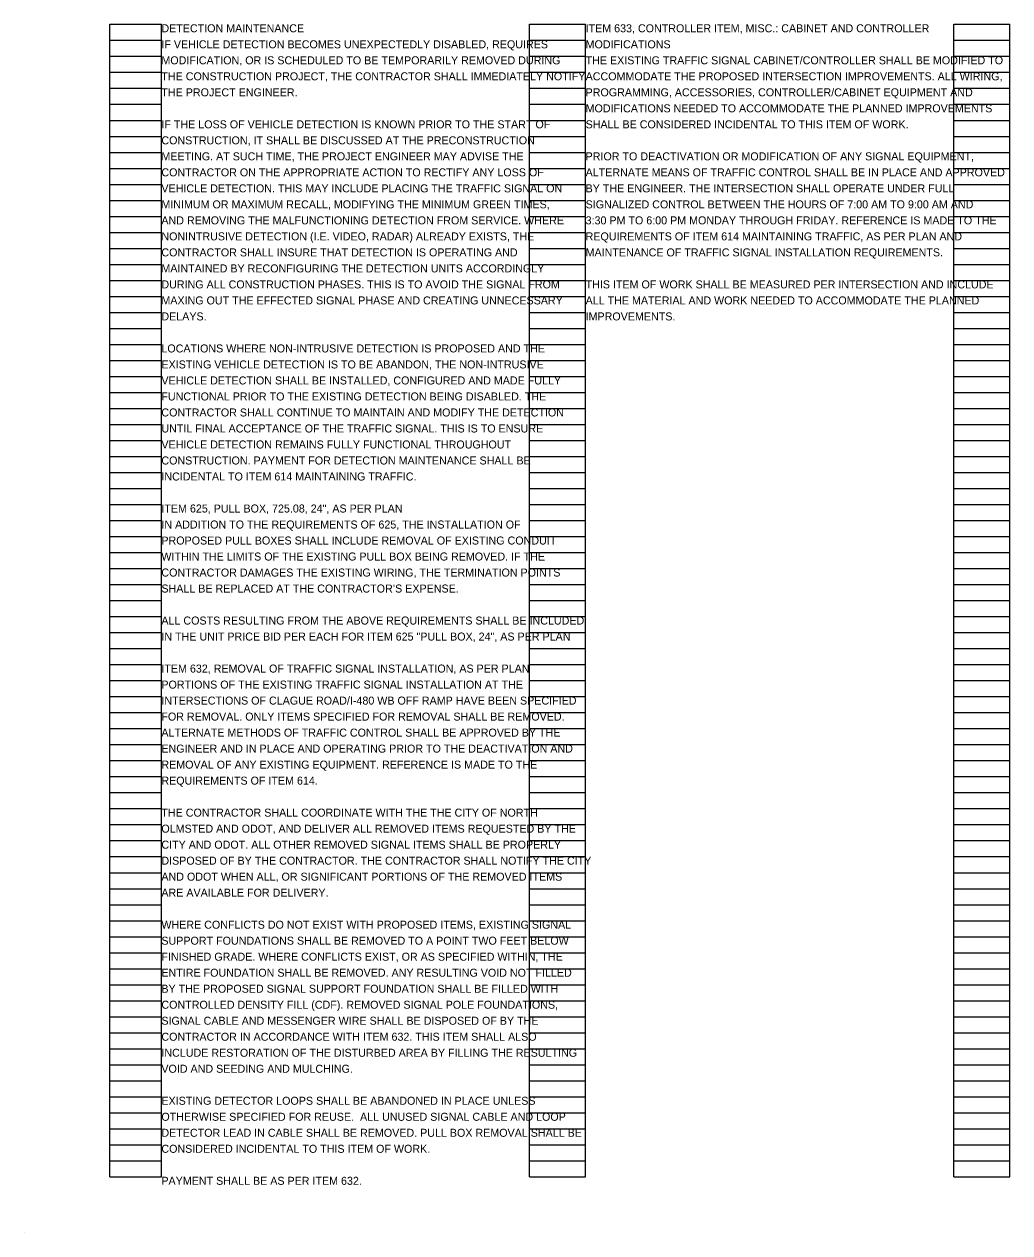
# Model space of a CAD drawing. Extents: x 0 to 34, y -30 to 22.
# Drawn here: x 0 to 17.24, y -30 to -8.86 of the extents above; entities that cross this region are included whole.
import ezdxf

# ---------------------------------------------------------------- set-up
doc = ezdxf.new("R2010")
doc.units = 0
doc.layers.add('SH_Data', color=7, linetype='Continuous')
doc.layers.add('SH_Text', color=7, linetype='Continuous')

msp = doc.modelspace()

# ---------------------------------------------------------------- linework, layer by layer
at = {"layer": 'SH_Data'}
for p, q in [((1.5, -29.02), (1.5, -8.86)), ((1.5, -8.86), (2.4, -8.86)), ((2.4, -29.02), (2.4, -8.86)), ((8.84, -29.02), (8.84, -8.86)), ((8.84, -8.86), (9.82, -8.86)), ((9.82, -29.02), (9.82, -8.86)), ((16.26, -29.02), (16.26, -8.86)), ((16.26, -8.86), (17.24, -8.86)), ((17.24, -29.02), (17.24, -8.86)), ((1.5, -9.14), (2.4, -9.14)), ((8.84, -9.14), (9.82, -9.14)), ((16.26, -9.14), (17.24, -9.14)), ((1.5, -9.42), (2.4, -9.42)), ((8.84, -9.42), (9.82, -9.42)), ((16.26, -9.42), (17.24, -9.42)), ((1.5, -9.7), (2.4, -9.7)), ((8.84, -9.7), (9.82, -9.7)), ((16.26, -9.7), (17.24, -9.7)), ((1.5, -9.98), (2.4, -9.98)), ((8.84, -9.98), (9.82, -9.98)), ((16.26, -9.98), (17.24, -9.98)), ((1.5, -10.26), (2.4, -10.26)), ((8.84, -10.26), (9.82, -10.26)), ((16.26, -10.26), (17.24, -10.26)), ((1.5, -10.54), (2.4, -10.54)), ((8.84, -10.54), (9.82, -10.54)), ((16.26, -10.54), (17.24, -10.54)), ((1.5, -10.82), (2.4, -10.82)), ((8.84, -10.82), (9.82, -10.82)), ((16.26, -10.82), (17.24, -10.82)), ((1.5, -11.1), (2.4, -11.1)), ((8.84, -11.1), (9.82, -11.1)), ((16.26, -11.1), (17.24, -11.1)), ((1.5, -11.38), (2.4, -11.38)), ((8.84, -11.38), (9.82, -11.38)), ((16.26, -11.38), (17.24, -11.38)), ((1.5, -11.66), (2.4, -11.66)), ((8.84, -11.66), (9.82, -11.66)), ((16.26, -11.66), (17.24, -11.66)), ((1.5, -11.94), (2.4, -11.94)), ((8.84, -11.94), (9.82, -11.94)), ((16.26, -11.94), (17.24, -11.94)), ((1.5, -12.22), (2.4, -12.22)), ((8.84, -12.22), (9.82, -12.22)), ((16.26, -12.22), (17.24, -12.22)), ((1.5, -12.5), (2.4, -12.5)), ((8.84, -12.5), (9.82, -12.5)), ((16.26, -12.5), (17.24, -12.5)), ((1.5, -12.78), (2.4, -12.78)), ((8.84, -12.78), (9.82, -12.78)), ((16.26, -12.78), (17.24, -12.78)), ((1.5, -13.06), (2.4, -13.06)), ((8.84, -13.06), (9.82, -13.06)), ((16.26, -13.06), (17.24, -13.06)), ((1.5, -13.34), (2.4, -13.34)), ((8.84, -13.34), (9.82, -13.34)), ((16.26, -13.34), (17.24, -13.34)), ((1.5, -13.62), (2.4, -13.62)), ((8.84, -13.62), (9.82, -13.62)), ((16.26, -13.62), (17.24, -13.62)), ((1.5, -13.9), (2.4, -13.9)), ((8.84, -13.9), (9.82, -13.9)), ((16.26, -13.9), (17.24, -13.9)), ((1.5, -14.18), (2.4, -14.18)), ((8.84, -14.18), (9.82, -14.18)), ((16.26, -14.18), (17.24, -14.18)), ((1.5, -14.46), (2.4, -14.46)), ((8.84, -14.46), (9.82, -14.46)), ((16.26, -14.46), (17.24, -14.46)), ((1.5, -14.74), (2.4, -14.74)), ((8.84, -14.74), (9.82, -14.74)), ((16.26, -14.74), (17.24, -14.74)), ((1.5, -15.02), (2.4, -15.02)), ((8.84, -15.02), (9.82, -15.02)), ((16.26, -15.02), (17.24, -15.02)), ((1.5, -15.3), (2.4, -15.3)), ((8.84, -15.3), (9.82, -15.3)), ((16.26, -15.3), (17.24, -15.3)), ((1.5, -15.58), (2.4, -15.58)), ((8.84, -15.58), (9.82, -15.58)), ((16.26, -15.58), (17.24, -15.58)), ((1.5, -15.86), (2.4, -15.86)), ((8.84, -15.86), (9.82, -15.86)), ((16.26, -15.86), (17.24, -15.86)), ((1.5, -16.14), (2.4, -16.14)), ((8.84, -16.14), (9.82, -16.14)), ((16.26, -16.14), (17.24, -16.14)), ((1.5, -16.42), (2.4, -16.42)), ((8.84, -16.42), (9.82, -16.42)), ((16.26, -16.42), (17.24, -16.42)), ((1.5, -16.7), (2.4, -16.7)), ((8.84, -16.7), (9.82, -16.7)), ((16.26, -16.7), (17.24, -16.7)), ((1.5, -16.98), (2.4, -16.98)), ((8.84, -16.98), (9.82, -16.98)), ((16.26, -16.98), (17.24, -16.98)), ((1.5, -17.26), (2.4, -17.26)), ((8.84, -17.26), (9.82, -17.26)), ((16.26, -17.26), (17.24, -17.26)), ((1.5, -17.54), (2.4, -17.54)), ((8.84, -17.54), (9.82, -17.54)), ((16.26, -17.54), (17.24, -17.54)), ((1.5, -17.82), (2.4, -17.82)), ((8.84, -17.82), (9.82, -17.82)), ((16.26, -17.82), (17.24, -17.82)), ((1.5, -18.1), (2.4, -18.1)), ((8.84, -18.1), (9.82, -18.1)), ((16.26, -18.1), (17.24, -18.1)), ((1.5, -18.38), (2.4, -18.38)), ((8.84, -18.38), (9.82, -18.38)), ((16.26, -18.38), (17.24, -18.38)), ((1.5, -18.66), (2.4, -18.66)), ((8.84, -18.66), (9.82, -18.66)), ((16.26, -18.66), (17.24, -18.66)), ((1.5, -18.94), (2.4, -18.94)), ((8.84, -18.94), (9.82, -18.94)), ((16.26, -18.94), (17.24, -18.94)), ((1.5, -19.22), (2.4, -19.22)), ((8.84, -19.22), (9.82, -19.22)), ((16.26, -19.22), (17.24, -19.22)), ((1.5, -19.5), (2.4, -19.5)), ((8.84, -19.5), (9.82, -19.5)), ((16.26, -19.5), (17.24, -19.5)), ((1.5, -19.78), (2.4, -19.78)), ((8.84, -19.78), (9.82, -19.78)), ((16.26, -19.78), (17.24, -19.78)), ((1.5, -20.06), (2.4, -20.06)), ((8.84, -20.06), (9.82, -20.06)), ((16.26, -20.06), (17.24, -20.06)), ((1.5, -20.34), (2.4, -20.34)), ((8.84, -20.34), (9.82, -20.34)), ((16.26, -20.34), (17.24, -20.34)), ((1.5, -20.62), (2.4, -20.62)), ((8.84, -20.62), (9.82, -20.62)), ((16.26, -20.62), (17.24, -20.62)), ((1.5, -20.9), (2.4, -20.9)), ((8.84, -20.9), (9.82, -20.9)), ((16.26, -20.9), (17.24, -20.9)), ((1.5, -21.18), (2.4, -21.18)), ((8.84, -21.18), (9.82, -21.18)), ((16.26, -21.18), (17.24, -21.18)), ((1.5, -21.46), (2.4, -21.46)), ((8.84, -21.46), (9.82, -21.46)), ((16.26, -21.46), (17.24, -21.46)), ((1.5, -21.74), (2.4, -21.74)), ((8.84, -21.74), (9.82, -21.74)), ((16.26, -21.74), (17.24, -21.74)), ((1.5, -22.02), (2.4, -22.02)), ((8.84, -22.02), (9.82, -22.02)), ((16.26, -22.02), (17.24, -22.02)), ((1.5, -22.3), (2.4, -22.3)), ((8.84, -22.3), (9.82, -22.3)), ((16.26, -22.3), (17.24, -22.3)), ((1.5, -22.58), (2.4, -22.58)), ((8.84, -22.58), (9.82, -22.58)), ((16.26, -22.58), (17.24, -22.58)), ((1.5, -22.86), (2.4, -22.86)), ((8.84, -22.86), (9.82, -22.86)), ((16.26, -22.86), (17.24, -22.86)), ((1.5, -23.14), (2.4, -23.14)), ((8.84, -23.14), (9.82, -23.14)), ((16.26, -23.14), (17.24, -23.14)), ((1.5, -23.42), (2.4, -23.42)), ((8.84, -23.42), (9.82, -23.42)), ((16.26, -23.42), (17.24, -23.42)), ((1.5, -23.7), (2.4, -23.7)), ((8.84, -23.7), (9.82, -23.7)), ((16.26, -23.7), (17.24, -23.7)), ((1.5, -23.98), (2.4, -23.98)), ((8.84, -23.98), (9.82, -23.98)), ((16.26, -23.98), (17.24, -23.98)), ((1.5, -24.26), (2.4, -24.26)), ((8.84, -24.26), (9.82, -24.26)), ((16.26, -24.26), (17.24, -24.26)), ((1.5, -24.54), (2.4, -24.54)), ((8.84, -24.54), (9.82, -24.54)), ((16.26, -24.54), (17.24, -24.54)), ((1.5, -24.82), (2.4, -24.82)), ((8.84, -24.82), (9.82, -24.82)), ((16.26, -24.82), (17.24, -24.82)), ((1.5, -25.1), (2.4, -25.1)), ((8.84, -25.1), (9.82, -25.1)), ((16.26, -25.1), (17.24, -25.1)), ((1.5, -25.38), (2.4, -25.38)), ((8.84, -25.38), (9.82, -25.38)), ((16.26, -25.38), (17.24, -25.38)), ((1.5, -25.66), (2.4, -25.66)), ((8.84, -25.66), (9.82, -25.66)), ((16.26, -25.66), (17.24, -25.66)), ((1.5, -25.94), (2.4, -25.94)), ((8.84, -25.94), (9.82, -25.94)), ((16.26, -25.94), (17.24, -25.94)), ((1.5, -26.22), (2.4, -26.22)), ((8.84, -26.22), (9.82, -26.22)), ((16.26, -26.22), (17.24, -26.22)), ((1.5, -26.5), (2.4, -26.5)), ((8.84, -26.5), (9.82, -26.5)), ((16.26, -26.5), (17.24, -26.5)), ((1.5, -26.78), (2.4, -26.78)), ((8.84, -26.78), (9.82, -26.78)), ((16.26, -26.78), (17.24, -26.78)), ((1.5, -27.06), (2.4, -27.06)), ((8.84, -27.06), (9.82, -27.06)), ((16.26, -27.06), (17.24, -27.06)), ((1.5, -27.34), (2.4, -27.34)), ((8.84, -27.34), (9.82, -27.34)), ((16.26, -27.34), (17.24, -27.34)), ((1.5, -27.62), (2.4, -27.62)), ((8.84, -27.62), (9.82, -27.62)), ((16.26, -27.62), (17.24, -27.62)), ((1.5, -27.9), (2.4, -27.9)), ((8.84, -27.9), (9.82, -27.9)), ((16.26, -27.9), (17.24, -27.9)), ((1.5, -28.18), (2.4, -28.18)), ((8.84, -28.18), (9.82, -28.18)), ((16.26, -28.18), (17.24, -28.18)), ((1.5, -28.46), (2.4, -28.46)), ((8.84, -28.46), (9.82, -28.46)), ((16.26, -28.46), (17.24, -28.46)), ((1.5, -28.74), (2.4, -28.74)), ((8.84, -28.74), (9.82, -28.74)), ((16.26, -28.74), (17.24, -28.74)), ((1.5, -29.02), (2.4, -29.02)), ((8.84, -29.02), (9.82, -29.02)), ((16.26, -29.02), (17.24, -29.02)), ((0, -30), (0, -30))]:
    msp.add_line(p, q, dxfattribs=at)

# ---------------------------------------------------------------- texts
at = {"layer": 'SH_Text'}
for s, p in [('DETECTION MAINTENANCE', (2.4, -9)), ('ITEM 633, CONTROLLER ITEM, MISC.: CABINET AND CONTROLLER ', (9.82, -9)), ('IF VEHICLE DETECTION BECOMES UNEXPECTEDLY DISABLED, REQUIRES ', (2.4, -9.28)), ('MODIFICATIONS', (9.82, -9.28)), ('MODIFICATION, OR IS SCHEDULED TO BE TEMPORARILY REMOVED DURING ', (2.4, -9.56)), ('THE EXISTING TRAFFIC SIGNAL CABINET/CONTROLLER SHALL BE MODIFIED TO ', (9.82, -9.56)), ('THE CONSTRUCTION PROJECT, THE CONTRACTOR SHALL IMMEDIATELY NOTIFY ', (2.4, -9.84)), ('ACCOMMODATE THE PROPOSED INTERSECTION IMPROVEMENTS. ALL WIRING, ', (9.82, -9.84)), ('THE PROJECT ENGINEER.', (2.4, -10.12)), ('PROGRAMMING, ACCESSORIES, CONTROLLER/CABINET EQUIPMENT AND ', (9.82, -10.12)), ('MODIFICATIONS NEEDED TO ACCOMMODATE THE PLANNED IMPROVEMENTS ', (9.82, -10.4)), ('IF THE LOSS OF VEHICLE DETECTION IS KNOWN PRIOR TO THE START OF ', (2.4, -10.68)), ('SHALL BE CONSIDERED INCIDENTAL TO THIS ITEM OF WORK.', (9.82, -10.68)), ('CONSTRUCTION, IT SHALL BE DISCUSSED AT THE PRECONSTRUCTION ', (2.4, -10.96)), ('MEETING. AT SUCH TIME, THE PROJECT ENGINEER MAY ADVISE THE ', (2.4, -11.24)), ('PRIOR TO DEACTIVATION OR MODIFICATION OF ANY SIGNAL EQUIPMENT, ', (9.82, -11.24)), ('CONTRACTOR ON THE APPROPRIATE ACTION TO RECTIFY ANY LOSS OF ', (2.4, -11.52)), ('ALTERNATE MEANS OF TRAFFIC CONTROL SHALL BE IN PLACE AND APPROVED ', (9.82, -11.52)), ('VEHICLE DETECTION. THIS MAY INCLUDE PLACING THE TRAFFIC SIGNAL ON ', (2.4, -11.8)), ('BY THE ENGINEER. THE INTERSECTION SHALL OPERATE UNDER FULL ', (9.82, -11.8)), ('MINIMUM OR MAXIMUM RECALL, MODIFYING THE MINIMUM GREEN TIMES, ', (2.4, -12.08)), ('SIGNALIZED CONTROL BETWEEN THE HOURS OF 7:00 AM TO 9:00 AM AND ', (9.82, -12.08)), ('AND REMOVING THE MALFUNCTIONING DETECTION FROM SERVICE. WHERE ', (2.4, -12.36)), ('3:30 PM TO 6:00 PM MONDAY THROUGH FRIDAY. REFERENCE IS MADE TO THE ', (9.82, -12.36)), ('NONINTRUSIVE DETECTION (I.E. VIDEO, RADAR) ALREADY EXISTS, THE ', (2.4, -12.64)), ('REQUIREMENTS OF ITEM 614 MAINTAINING TRAFFIC, AS PER PLAN AND ', (9.82, -12.64)), ('CONTRACTOR SHALL INSURE THAT DETECTION IS OPERATING AND ', (2.4, -12.92)), ('MAINTENANCE OF TRAFFIC SIGNAL INSTALLATION REQUIREMENTS.', (9.82, -12.92)), ('MAINTAINED BY RECONFIGURING THE DETECTION UNITS ACCORDINGLY ', (2.4, -13.2)), ('DURING ALL CONSTRUCTION PHASES. THIS IS TO AVOID THE SIGNAL FROM ', (2.4, -13.48)), ('THIS ITEM OF WORK SHALL BE MEASURED PER INTERSECTION AND INCLUDE ', (9.82, -13.48)), ('MAXING OUT THE EFFECTED SIGNAL PHASE AND CREATING UNNECESSARY ', (2.4, -13.76)), ('ALL THE MATERIAL AND WORK NEEDED TO ACCOMMODATE THE PLANNED ', (9.82, -13.76)), ('DELAYS.', (2.4, -14.04)), ('IMPROVEMENTS.', (9.82, -14.04)), ('LOCATIONS WHERE NON-INTRUSIVE DETECTION IS PROPOSED AND THE ', (2.4, -14.6)), ('EXISTING VEHICLE DETECTION IS TO BE ABANDON, THE NON-INTRUSIVE ', (2.4, -14.88)), ('VEHICLE DETECTION SHALL BE INSTALLED, CONFIGURED AND MADE FULLY ', (2.4, -15.16)), ('FUNCTIONAL PRIOR TO THE EXISTING DETECTION BEING DISABLED. THE ', (2.4, -15.44)), ('CONTRACTOR SHALL CONTINUE TO MAINTAIN AND MODIFY THE DETECTION ', (2.4, -15.72)), ('UNTIL FINAL ACCEPTANCE OF THE TRAFFIC SIGNAL. THIS IS TO ENSURE ', (2.4, -16)), ('VEHICLE DETECTION REMAINS FULLY FUNCTIONAL THROUGHOUT ', (2.4, -16.28)), ('CONSTRUCTION. PAYMENT FOR DETECTION MAINTENANCE SHALL BE ', (2.4, -16.56)), ('INCIDENTAL TO ITEM 614 MAINTAINING TRAFFIC.', (2.4, -16.84)), ('ITEM 625, PULL BOX, 725.08, 24", AS PER PLAN', (2.4, -17.4)), ('IN ADDITION TO THE REQUIREMENTS OF 625, THE INSTALLATION OF ', (2.4, -17.68)), ('PROPOSED PULL BOXES SHALL INCLUDE REMOVAL OF EXISTING CONDUIT ', (2.4, -17.96)), ('WITHIN THE LIMITS OF THE EXISTING PULL BOX BEING REMOVED. IF THE ', (2.4, -18.24)), ('CONTRACTOR DAMAGES THE EXISTING WIRING, THE TERMINATION POINTS ', (2.4, -18.52)), ('SHALL BE REPLACED AT THE CONTRACTOR’S EXPENSE.', (2.4, -18.8)), ('ALL COSTS RESULTING FROM THE ABOVE REQUIREMENTS SHALL BE INCLUDED ', (2.4, -19.36)), ('IN THE UNIT PRICE BID PER EACH FOR ITEM 625 "PULL BOX, 24", AS PER PLAN', (2.4, -19.64)), ('ITEM 632, REMOVAL OF TRAFFIC SIGNAL INSTALLATION, AS PER PLAN', (2.4, -20.2)), ('PORTIONS OF THE EXISTING TRAFFIC SIGNAL INSTALLATION AT THE ', (2.4, -20.48)), ('INTERSECTIONS OF CLAGUE ROAD/I-480 WB OFF RAMP HAVE BEEN SPECIFIED ', (2.4, -20.76)), ('FOR REMOVAL. ONLY ITEMS SPECIFIED FOR REMOVAL SHALL BE REMOVED. ', (2.4, -21.04)), ('ALTERNATE METHODS OF TRAFFIC CONTROL SHALL BE APPROVED BY THE ', (2.4, -21.32)), ('ENGINEER AND IN PLACE AND OPERATING PRIOR TO THE DEACTIVATION AND ', (2.4, -21.6)), ('REMOVAL OF ANY EXISTING EQUIPMENT. REFERENCE IS MADE TO THE ', (2.4, -21.88)), ('REQUIREMENTS OF ITEM 614.', (2.4, -22.16)), ('THE CONTRACTOR SHALL COORDINATE WITH THE THE CITY OF NORTH ', (2.4, -22.72)), ('OLMSTED AND ODOT, AND DELIVER ALL REMOVED ITEMS REQUESTED BY THE ', (2.4, -23)), ('CITY AND ODOT. ALL OTHER REMOVED SIGNAL ITEMS SHALL BE PROPERLY ', (2.4, -23.28)), ('DISPOSED OF BY THE CONTRACTOR. THE CONTRACTOR SHALL NOTIFY THE CITY ', (2.4, -23.56)), ('AND ODOT WHEN ALL, OR SIGNIFICANT PORTIONS OF THE REMOVED ITEMS ', (2.4, -23.84)), ('ARE AVAILABLE FOR DELIVERY.', (2.4, -24.12)), ('WHERE CONFLICTS DO NOT EXIST WITH PROPOSED ITEMS, EXISTING SIGNAL ', (2.4, -24.68)), ('SUPPORT FOUNDATIONS SHALL BE REMOVED TO A POINT TWO FEET BELOW ', (2.4, -24.96)), ('FINISHED GRADE. WHERE CONFLICTS EXIST, OR AS SPECIFIED WITHIN, THE ', (2.4, -25.24)), ('ENTIRE FOUNDATION SHALL BE REMOVED. ANY RESULTING VOID NOT FILLED ', (2.4, -25.52)), ('BY THE PROPOSED SIGNAL SUPPORT FOUNDATION SHALL BE FILLED WITH ', (2.4, -25.8)), ('CONTROLLED DENSITY FILL (CDF). REMOVED SIGNAL POLE FOUNDATIONS, ', (2.4, -26.08)), ('SIGNAL CABLE AND MESSENGER WIRE SHALL BE DISPOSED OF BY THE ', (2.4, -26.36)), ('CONTRACTOR IN ACCORDANCE WITH ITEM 632. THIS ITEM SHALL ALSO ', (2.4, -26.64)), ('INCLUDE RESTORATION OF THE DISTURBED AREA BY FILLING THE RESULTING ', (2.4, -26.92)), ('VOID AND SEEDING AND MULCHING.', (2.4, -27.2)), ('EXISTING DETECTOR LOOPS SHALL BE ABANDONED IN PLACE UNLESS ', (2.4, -27.76)), ('OTHERWISE SPECIFIED FOR REUSE.  ALL UNUSED SIGNAL CABLE AND LOOP ', (2.4, -28.04)), ('DETECTOR LEAD IN CABLE SHALL BE REMOVED. PULL BOX REMOVAL SHALL BE ', (2.4, -28.32)), ('CONSIDERED INCIDENTAL TO THIS ITEM OF WORK. ', (2.4, -28.6)), ('PAYMENT SHALL BE AS PER ITEM 632.', (2.4, -29.16))]:
    msp.add_text(s, height=0.14, dxfattribs=at).set_placement(p)

doc.saveas('drawing.dxf')
